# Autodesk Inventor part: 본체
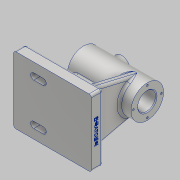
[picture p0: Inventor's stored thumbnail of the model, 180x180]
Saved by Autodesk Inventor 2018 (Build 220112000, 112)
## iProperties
Created: 2022-06
Part Number: 본체
Material: 알루미늄 6061
Document SubType Name: Modeling
Designer: home
Density: 2.7 g/cm^3
Appearance: 알루미늄 - 평지
Mass: 633.804 g
Surface Area: 513.531 cm^2
Volume: 234.742 cm^3
Author: home
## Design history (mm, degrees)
sketch "스케치1"
  geometry: L1 (50, -43)-(-50, -43); L2 (-50, -43)-(-50, 43); L3 (-50, 43)-(50, 43); L4 (50, 43)-(50, -43); 3 further points
  constraints: 8 end point, 2 midpoint, 2 parallel, 1 horizontal, 1 horizontal alignment, 1 perpendicular, 1 vertical alignment
  dimensions: "d0" = 100 distance of L1.start L1.end; "d1" = 86 distance of L1.end L2.end
extrude "돌출1" new body sketch "스케치1" distance "d2" = 15; taper "d3" = 0 deg
sketch "스케치2"
  geometry: L1 (-66.86, 72)-(81.788, 72); L2 (-50, 0)-(50, 0) reference; L3 (50, 83.5)-(50, 93); L4 (50, 93)-(-32, 93); L5 (-32, 93)-(-32, 86.5); L6 (50, 83.5)-(30, 83.5); L7 (30, 83.5)-(30, 86.5); L8 (30, 86.5)-(-32, 86.5); 2 further points
  constraints: 14 end point, 4 perpendicular, 2 horizontal, 1 midpoint, 1 vertical, 1 vertical alignment
  dimensions: "d4" = 72 distance between parallel lines of L2 L1; "d5" = 82 distance of L3.end L4.end; "d6" = 29 diameter of L8 L1; "d7" = 42 diameter of L4 L1; "d8" = 23 diameter of L6 L1; "d9" = 62 distance of L7.end L5.end
revolve "회전1" sketch "스케치2" stored, may be unused: angle "d10" = 90 deg
node "작업 평면1"
sketch "스케치4"
  geometry: L1 (8, 15)-(22.559, 76.814); L2 (78, 15)-(63.441, 76.814); L3 (86, 15)-(0, 15) reference; L4 (0, 0)-(0, 15) reference; L5 (86, 0)-(86, 15) reference; A1 r 21 centre (43, 72) between (22.559, 76.814) and (63.441, 76.814) reference; 1 further point
  constraints: 4 end point, 2 point on circle, 2 point on line, 2 tangent
  dimensions: "d15" = 8 distance from line of L4 L1.start; "d16" = 8 distance from line of L5 L2.start
extrude "돌출2" join sketch "스케치4" distance "d17" = 10; taper "d18" = 0 deg
sketch "스케치5"
  geometry: L1 (-35, 15)-(-21.897, 51); L2 (50, 15)-(-50, 15) reference; L3 (-32, 51)-(50, 51) reference; L4 (-50, 0)-(-50, 15) reference; 1 further point
  constraints: 2 end point, 2 point on line
  dimensions: "d19" = 15 distance from line of L4 L1.start; "d20" = 70 deg angle of L2 L1
feature "리브1" sketch "스케치5" dims "d21" = 1, "d22" = 10, "d23" = 0, "d24" = 0, "d25" = 1, "d26" = 1
sketch "스케치6"
  geometry: C1 r 21 at (0, 0) reference; 2 further points
  constraints: 1 vertical alignment
  dimensions: "d27" = 18 distance of C1.centre point (0, 18)
hole "구멍1" sketch "스케치6" at (0, 18) diameter "d28" = 2.459; stored, may be unused: countersink angle "d32" = 90 deg, drill point angle "d34" = 118 deg; dims "d29" = 8, "d30" = 4, "d31" = 2, "d33" = 10
sketch "스케치7"
  geometry: C1 r 1.23 at (0, 18) reference; C2 r 21 at (0, 0) reference; 2 further points
  constraints: 1 coincident
hole "구멍2" sketch "스케치7" at (0, 18) diameter "d38" = 2.459; stored, may be unused: countersink angle "d42" = 90 deg, drill point angle "d44" = 118 deg; dims "d39" = 8, "d40" = 4, "d41" = 2, "d43" = 10
sketch "스케치8"
  geometry: L1 (-24, 27)-(-12, 27); L2 (-24, 20)-(-12, 20); L3 (-12, 34)-(-24, 34); L4 (-50, -43)-(-50, 43) reference; L5 (-50, 43)-(50, 43) reference; A1 r 7 centre (-24, 27) between (-24, 34) and (-24, 20); A2 r 7 centre (-12, 27) between (-12, 20) and (-12, 34); 2 further points
  constraints: 8 end point, 4 point on circle, 4 tangent, 2 centre point, 1 horizontal, 1 midpoint, 1 parallel
  dimensions: "d48" = 12 distance of L1.start L1.end; "d49" = 26 distance from line of L4 L1.start; "d50" = 14 distance between parallel lines of L3 L2; "d51" = 16 distance between parallel lines of L5 L1
extrude "돌출3" join sketch "스케치8" distance "d52" = 3; taper "d53" = 0 deg
sketch "스케치9"
  geometry: L1 (-24, 20)-(-12, 20) reference; L2 (-12, 34)-(-24, 34) reference; L3 (-12, 23)-(-24, 23); L4 (-24, 31)-(-12, 31); A1 r 7 centre (-12, 27) between (-12, 20) and (-12, 34) reference; A2 r 7 centre (-24, 27) between (-24, 34) and (-24, 20) reference; A3 r 4 centre (-12, 27) between (-12, 23) and (-12, 31); A4 r 4 centre (-24, 27) between (-24, 31) and (-24, 23); 1 further point
  constraints: 4 end point, 4 point on circle, 2 centre point, 3 other
  dimensions: "d54" = 3 radial gap between concentric circles of A1 A3
extrude "돌출4" cut sketch "스케치9" extent not by distance; stored distance "d55" = 3; taper "d56" = 0 deg
fillet "모깎기1" dims "d57" = 3
node "작업 평면2"
sketch "스케치10"
  geometry: L1 (32, 21)-(32, -21) reference; C1 r 11 at (7, 0); 1 further point
  constraints: 1 centre point, 1 horizontal alignment
  dimensions: "d59" = 22 diameter of C1; "d60" = 25 distance from line of L1 C1.centre
extrude "돌출5" join sketch "스케치10" stored distance "d61" = 3; taper "d62" = 0 deg
sketch "스케치11"
  geometry: C1 r 11 at (0, 0) reference; 1 further point
hole "구멍3" sketch "스케치11" at (0, 0) diameter "d63" = 4.917; stored, may be unused: countersink angle "d67" = 90 deg, drill point angle "d69" = 118 deg; dims "d64" = 12, "d65" = 14, "d66" = 4, "d68" = 17.1
node "작업 평면3"
sketch "스케치12"
  geometry: 2 further points
  constraints: 1 horizontal alignment, 1 other
  dimensions: "d71" = 6 distance of point (0, 0) point (6, 0)
feature "엠보싱1" sketch "스케치12" dims "d0" = 100, "d1" = 86, "d9" = 62, "d72" = 0.5, "d73" = 0
fillet "모깎기2" dims "d74" = 3
fillet "모깎기3" dims "d75" = 3
chamfer "모따기1" distance "d76" = 1; stored, may be unused: second distance "d77" = 2, angle "d78" = 45 deg
fillet "모깎기4" dims "d79" = 3
fillet "모깎기5" dims "d80" = 3
fillet "모깎기6" dims "d81" = 1
node "솔리드1"
pattern_circular "원형 패턴1" dims angle "d36" = 360 deg
pattern_circular "원형 패턴2" dims angle "d46" = 360 deg
mirror "미러1"
node "투영된 루프1"
other parameters: "d14" = -15, "d58" = 96, "d70" = 72
